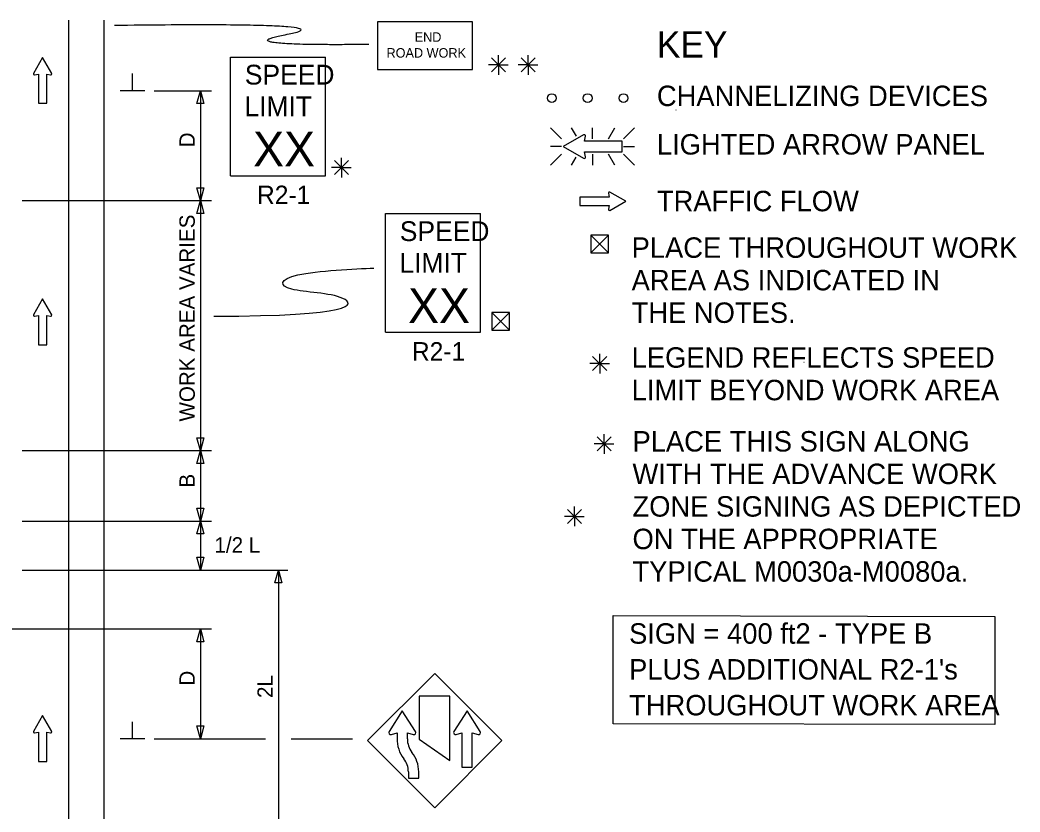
# Model space of a CAD drawing. Extents: x 16648 to 18482, y 5650 to 7013.
# Drawn here: x 16969.3 to 17424.3, y 6566.2 to 6926.4 of the extents above; entities that cross this region are included whole.
import ezdxf

# ---------------------------------------------------------------- set-up
doc = ezdxf.new("R2010")
doc.units = 0
for name, color, linetype in [('MT_SCRATCH_LEVEL_E', 7, 'Continuous'), ('PAVT_EDGE_EX', 7, 'Continuous'), ('TRAFFIC_SIGNS_PR', 7, 'Continuous'), ('TYPICAL_TEXT_DIMEN_EX', 7, 'Continuous'), ('TYPICAL_TEXT_DIMEN_PR', 7, 'Continuous')]:
    doc.layers.add(name, color=color, linetype=linetype)

msp = doc.modelspace()

# ---------------------------------------------------------------- linework, layer by layer
at = {"layer": 'MT_SCRATCH_LEVEL_E'}
for p, q in [((16979.53, 6909.41), (16975.42, 6902.17)), ((16983.68, 6902.17), (16979.53, 6909.41)), ((16975.91, 6901.48), (16977.68, 6901.8)), ((16977.68, 6901.8), (16977.68, 6888.54)), ((16981.42, 6888.54), (16981.42, 6901.8)), ((16981.42, 6901.8), (16983.2, 6901.48)), ((16977.68, 6888.54), (16981.42, 6888.54)), ((17236.96, 6847.63), (17237.27, 6845.86)), ((17244.88, 6844.01), (17237.64, 6848.12)), ((17237.27, 6845.86), (17224.01, 6845.86)), ((17224.01, 6845.86), (17224.01, 6842.11)), ((17237.64, 6839.86), (17244.88, 6844.01)), ((17224.01, 6842.11), (17237.27, 6842.11)), ((17237.27, 6842.11), (17236.96, 6840.34)), ((16979.53, 6799.6), (16975.42, 6792.36)), ((16983.68, 6792.36), (16979.53, 6799.6)), ((16975.91, 6791.67), (16977.68, 6791.99)), ((16977.68, 6791.99), (16977.68, 6778.73)), ((16981.42, 6778.73), (16981.42, 6791.99)), ((16981.42, 6791.99), (16983.2, 6791.67)), ((16977.68, 6778.73), (16981.42, 6778.73)), ((16979.53, 6610.04), (16975.42, 6602.8)), ((16983.68, 6602.8), (16979.53, 6610.04)), ((16975.91, 6602.12), (16977.68, 6602.43)), ((16977.68, 6602.43), (16977.68, 6589.18)), ((16981.42, 6589.18), (16981.42, 6602.43)), ((16981.42, 6602.43), (16983.2, 6602.12)), ((16977.68, 6589.18), (16981.42, 6589.18))]:
    msp.add_line(p, q, dxfattribs=at)
for centre, start, end in [((16975.83, 6901.94), 150.4248, 279.9638), ((16983.27, 6901.94), 260.0362, 29.7731), ((17237.41, 6847.71), 60.4248, 189.9638), ((17237.42, 6840.27), 170.0362, 299.7731), ((16975.83, 6792.13), 150.4248, 279.9638), ((16983.27, 6792.13), 260.0362, 29.7731), ((16975.83, 6602.58), 150.4248, 279.9638), ((16983.27, 6602.58), 260.0362, 29.7731)]:
    msp.add_arc(centre, 0.463, start, end, dxfattribs=at)
at = {"layer": 'PAVT_EDGE_EX'}
for p, q in [((16991.36, 6926.44), (16991.36, 5975.16)), ((17007.36, 6926.44), (17007.36, 5975.16))]:
    msp.add_line(p, q, dxfattribs=at)
at = {"layer": 'TRAFFIC_SIGNS_PR'}
for p, q in [((17065.08, 6909.61), (17108.28, 6909.61)), ((17065.08, 6855.61), (17065.08, 6909.61)), ((17108.28, 6855.61), (17108.28, 6909.61)), ((17210.69, 6877.39), (17215.62, 6872.46)), ((17222.45, 6873.57), (17220.25, 6877.39)), ((17229.77, 6872.46), (17229.77, 6877.39)), ((17237.01, 6872.46), (17239.86, 6877.39)), ((17243.92, 6872.46), (17248.86, 6877.39)), ((17215.62, 6868.9), (17210.69, 6868.9)), ((17243.92, 6868.9), (17248.86, 6868.9)), ((17210.69, 6860.41), (17215.62, 6865.34)), ((17220.2, 6860.41), (17222.32, 6864.07)), ((17229.77, 6865.34), (17229.77, 6860.41)), ((17239.9, 6860.41), (17237.05, 6865.34)), ((17243.92, 6865.34), (17248.86, 6860.41)), ((17065.08, 6855.61), (17108.28, 6855.61)), ((17135.57, 6838.41), (17178.77, 6838.41)), ((17135.57, 6784.41), (17135.57, 6838.41)), ((17178.77, 6784.41), (17178.77, 6838.41)), ((17135.57, 6784.41), (17178.77, 6784.41)), ((17157.98, 6629.21), (17127.43, 6598.66)), ((17188.53, 6598.66), (17157.98, 6629.21)), ((17127.43, 6598.66), (17157.98, 6568.11)), ((17157.98, 6568.11), (17188.53, 6598.66))]:
    msp.add_line(p, q, dxfattribs=at)
for points in [[(17131.96, 6904), (17175.16, 6904), (17175.16, 6925.6), (17131.96, 6925.6)], [(17150.88, 6618.83), (17150.88, 6599.32), (17164.84, 6589.62), (17164.84, 6618.83)]]:
    msp.add_lwpolyline(points, close=True, dxfattribs=at)
for points in [[(17225.7, 6874.18), (17216.41, 6868.9), (17225.7, 6863.58)], [(17226.58, 6864.21), (17226.18, 6866.47), (17243.19, 6866.47), (17243.19, 6871.28), (17226.18, 6871.28), (17226.58, 6873.56)], [(17149.2, 6602.83), (17143.2, 6612.24), (17137.21, 6602.83)], [(17178.7, 6602.83), (17172.71, 6612.24), (17166.72, 6602.83)], [(17138.26, 6601.41), (17140.84, 6602.12), (17140.84, 6599.61)], [(17145.56, 6599.49), (17145.56, 6602.12), (17148.15, 6601.41)], [(17167.77, 6601.41), (17170.35, 6602.12), (17170.35, 6586.59), (17175.07, 6586.59), (17175.07, 6602.12), (17177.66, 6601.41)], [(17145.98, 6584.47), (17145.97, 6581.49), (17150.7, 6581.49), (17150.7, 6584.47)]]:
    msp.add_lwpolyline(points, dxfattribs=at)
for centre in [(17211.26, 6890.93), (17227.56, 6890.93), (17243.86, 6890.93)]:
    msp.add_circle(centre, 2, dxfattribs=at)
for centre, radius, start, end in [((17225.99, 6873.65), 0.598, 350.7308, 118.8916), ((17225.99, 6864.1), 0.597, 241.4833, 9.9593), ((17138.01, 6602.32), 0.945, 147.5204, 285.3986), ((17148.4, 6602.32), 0.947, 254.6828, 32.2708), ((17159.16, 6609.16), 11.81, 212.4569, 212.4665), ((17167.52, 6602.32), 0.946, 147.5497, 285.3316), ((17177.91, 6602.32), 0.943, 254.6778, 32.4665), ((17188.67, 6609.16), 11.81, 212.4569, 212.4665), ((17155, 6599.19), 14.17, 178.3293, 218.5427), ((17155, 6599.19), 9.45, 178.1936, 218.5465), ((17133.75, 6599.86), 11.81, 358.1894, 0.0048), ((17145.03, 6590.01), 11.81, 74.68, 74.6808), ((17136.52, 6584.47), 14.17, 0, 38.5422), ((17136.52, 6584.47), 9.45, 0, 38.5457)]:
    msp.add_arc(centre, radius, start, end, dxfattribs=at)
msp.add_open_spline([(17127.94, 6915.32), (17061.52, 6914.54), (17120.27, 6925.35), (17012.29, 6923.93)], degree=2, dxfattribs=at)
at = {"layer": 'TYPICAL_TEXT_DIMEN_EX'}
msp.add_lwpolyline([(17239.16, 6655.51), (17412.83, 6655.12), (17412.83, 6605.93), (17239.16, 6606.31)], close=True, dxfattribs=at)
at = {"layer": 'TYPICAL_TEXT_DIMEN_PR'}
for p, q in [((17183.74, 6909.19), (17190.11, 6902.81)), ((17190.11, 6909.19), (17183.74, 6902.81)), ((17186.92, 6906), (17186.92, 6910.45)), ((17197.24, 6909.19), (17203.62, 6902.81)), ((17203.62, 6909.19), (17197.24, 6902.81)), ((17200.43, 6906), (17200.43, 6910.45)), ((17020.48, 6894.29), (17020.48, 6902.08)), ((17186.92, 6906), (17182.39, 6906)), ((17186.92, 6906), (17190.11, 6906)), ((17186.92, 6906), (17191.4, 6906)), ((17186.92, 6906), (17186.92, 6901.5)), ((17200.43, 6906), (17195.9, 6906)), ((17200.43, 6906), (17203.62, 6906)), ((17200.43, 6906), (17204.91, 6906)), ((17200.43, 6906), (17200.43, 6901.5)), ((17026.11, 6894.29), (17014.86, 6894.29)), ((17030.36, 6894.29), (17056.36, 6894.29)), ((17049.79, 6888.43), (17051.36, 6894.29)), ((17051.36, 6894.29), (17051.36, 6844.29)), ((17051.36, 6894.29), (17052.93, 6888.43)), ((17051.36, 6888.43), (17049.79, 6888.43)), ((17052.93, 6888.43), (17051.36, 6888.43)), ((17112.35, 6862.56), (17118.72, 6856.18)), ((17118.72, 6862.56), (17112.35, 6856.18)), ((17115.53, 6859.37), (17115.53, 6863.82)), ((17115.53, 6859.37), (17111, 6859.37)), ((17115.53, 6859.37), (17118.72, 6859.37)), ((17115.53, 6859.37), (17120.01, 6859.37)), ((17115.53, 6859.37), (17115.53, 6854.87)), ((17051.36, 6844.29), (17049.79, 6850.15)), ((17049.79, 6850.15), (17051.36, 6850.15)), ((17051.36, 6850.15), (17052.93, 6850.15)), ((17052.93, 6850.15), (17051.36, 6844.29)), ((16970.29, 6844.29), (17056.36, 6844.29)), ((17049.79, 6838.43), (17051.36, 6844.29)), ((17051.36, 6844.29), (17051.36, 6730.57)), ((17051.36, 6844.29), (17052.93, 6838.43)), ((17051.36, 6838.43), (17049.79, 6838.43)), ((17052.93, 6838.43), (17051.36, 6838.43)), ((17229.05, 6828.52), (17237.05, 6820.52)), ((17229.05, 6820.52), (17237.05, 6828.52)), ((17183.93, 6793.35), (17191.93, 6785.35)), ((17183.93, 6785.35), (17191.93, 6793.35)), ((17233.01, 6770.17), (17228.48, 6770.17)), ((17229.82, 6773.36), (17236.2, 6766.98)), ((17236.2, 6773.36), (17229.82, 6766.98)), ((17233.01, 6770.17), (17233.01, 6774.63)), ((17233.01, 6770.17), (17236.2, 6770.17)), ((17233.01, 6770.17), (17237.49, 6770.17)), ((17233.01, 6770.17), (17233.01, 6765.67)), ((17051.36, 6730.57), (17049.79, 6736.43)), ((17049.79, 6736.43), (17051.36, 6736.43)), ((17051.36, 6736.43), (17052.93, 6736.43)), ((17052.93, 6736.43), (17051.36, 6730.57)), ((17231.82, 6736.83), (17238.2, 6730.45)), ((17238.2, 6736.83), (17231.82, 6730.45)), ((17235.01, 6733.64), (17235.01, 6738.1)), ((16970.29, 6730.57), (17056.36, 6730.57)), ((17049.79, 6724.7), (17051.36, 6730.57)), ((17051.36, 6730.57), (17051.36, 6698.49)), ((17051.36, 6730.57), (17052.93, 6724.7)), ((17235.01, 6733.64), (17230.48, 6733.64)), ((17235.01, 6733.64), (17238.2, 6733.64)), ((17235.01, 6733.64), (17239.49, 6733.64)), ((17235.01, 6733.64), (17235.01, 6729.14)), ((17051.36, 6724.7), (17049.79, 6724.7)), ((17052.93, 6724.7), (17051.36, 6724.7)), ((17051.36, 6698.49), (17049.79, 6704.35)), ((17049.79, 6704.35), (17051.36, 6704.35)), ((17051.36, 6705.58), (17051.36, 6701.99)), ((17051.36, 6704.35), (17052.93, 6704.35)), ((17052.93, 6704.35), (17051.36, 6698.49)), ((17218.32, 6703.83), (17224.69, 6697.45)), ((17224.69, 6703.83), (17218.32, 6697.45)), ((17221.5, 6700.64), (17221.5, 6705.1)), ((16970.29, 6698.49), (17056.36, 6698.49)), ((17049.79, 6692.63), (17051.36, 6698.49)), ((17051.36, 6698.49), (17051.36, 6676.24)), ((17051.36, 6698.49), (17052.93, 6692.63)), ((17221.5, 6700.64), (17216.97, 6700.64)), ((17221.5, 6700.64), (17224.69, 6700.64)), ((17221.5, 6700.64), (17225.98, 6700.64)), ((17221.5, 6700.64), (17221.5, 6696.14)), ((17051.36, 6692.63), (17049.79, 6692.63)), ((17052.93, 6692.63), (17051.36, 6692.63)), ((17051.36, 6676.24), (17049.79, 6682.11)), ((17049.79, 6682.11), (17051.36, 6682.11)), ((17051.36, 6682.11), (17052.93, 6682.11)), ((17052.93, 6682.11), (17051.36, 6676.24)), ((16970.29, 6676.24), (17091.17, 6676.24)), ((17085.27, 6670.38), (17086.84, 6676.24)), ((17086.84, 6676.24), (17086.84, 6558.37)), ((17086.84, 6676.24), (17088.41, 6670.38)), ((17086.84, 6670.38), (17085.27, 6670.38)), ((17088.41, 6670.38), (17086.84, 6670.38)), ((16951.51, 6649.44), (17056.36, 6649.44)), ((17049.79, 6643.58), (17051.36, 6649.44)), ((17051.36, 6649.44), (17051.36, 6599.44)), ((17051.36, 6649.44), (17052.93, 6643.58)), ((17051.36, 6643.58), (17049.79, 6643.58)), ((17052.93, 6643.58), (17051.36, 6643.58)), ((17020.48, 6599.44), (17020.48, 6607.22)), ((17051.36, 6599.44), (17049.79, 6605.3)), ((17049.79, 6605.3), (17051.36, 6605.3)), ((17051.36, 6605.3), (17052.93, 6605.3)), ((17052.93, 6605.3), (17051.36, 6599.44)), ((17026.11, 6599.44), (17014.86, 6599.44)), ((17030.36, 6599.44), (17080.98, 6599.44)), ((17092.7, 6599.44), (17120.51, 6599.44))]:
    msp.add_line(p, q, dxfattribs=at)
for points in [[(17229.05, 6828.52), (17229.05, 6820.52), (17237.05, 6820.52), (17237.05, 6828.52)], [(17183.93, 6793.35), (17183.93, 6785.35), (17191.93, 6785.35), (17191.93, 6793.35)]]:
    msp.add_lwpolyline(points, close=True, dxfattribs=at)
for points, degree in [([(17267.72, 6885.65), (17267.73, 6885.65), (17267.74, 6885.65), (17267.74, 6885.65)], 2), ([(17057.4, 6791.72), (17121.98, 6791.72), (17121.98, 6802.48), (17087.07, 6802.48), (17087.07, 6811.56), (17121.76, 6813.31), (17130.31, 6813.6)], 3), ([(17325.96, 6770.76), (17325.98, 6770.76), (17325.99, 6770.76), (17325.99, 6770.76)], 2)]:
    msp.add_open_spline(points, degree=degree, dxfattribs=at)

# ---------------------------------------------------------------- texts
at = {"layer": 'TRAFFIC_SIGNS_PR'}
for s, height, p in [('END', 4.31, (17148.84, 6916.52)), ('ROAD WORK', 4.31, (17136.02, 6909.34)), ('SPEED', 9, (17071.56, 6897.08)), ('LIMIT', 9, (17071.38, 6882.68)), ('XX', 15.785, (17075.33, 6859.84)), ('R2-1', 8.37, (17077.09, 6842.74)), ('SPEED', 9, (17142.06, 6825.88)), ('LIMIT', 9, (17141.88, 6811.48)), ('XX', 15.785, (17145.83, 6788.64)), ('R2-1', 8.37, (17147.58, 6771.54)), ('PLACE THIS SIGN ALONG', 9.3, (17247.95, 6730.14)), ('WITH THE ADVANCE WORK', 9.3, (17247.95, 6715.34)), ('ZONE SIGNING AS DEPICTED', 9.3, (17247.95, 6700.54)), ('ON THE APPROPRIATE', 9.3, (17247.95, 6685.74)), ('TYPICAL M0030a-M0080a.', 9.3, (17247.95, 6670.94))]:
    msp.add_text(s, height=height, dxfattribs=at).set_placement(p)
at = {"layer": 'TYPICAL_TEXT_DIMEN_EX'}
for s, height, p in [('KEY', 12, (17259.05, 6909.34)), ('CHANNELIZING DEVICES', 9.3, (17259.05, 6887.29)), ('LIGHTED ARROW PANEL', 9.3, (17259.05, 6865.24)), ('TRAFFIC FLOW', 9.3, (17259.05, 6839.44)), ('PLACE THROUGHOUT WORK', 9.3, (17247.55, 6818.26)), ('AREA AS INDICATED IN', 9.3, (17247.55, 6803.46)), ('THE NOTES.', 9.3, (17247.55, 6788.66)), ('LEGEND REFLECTS SPEED', 9.3, (17247.56, 6768.27)), ('LIMIT BEYOND WORK AREA', 9.3, (17247.56, 6753.47)), ('SIGN = 400 ft2 - TYPE B', 9.3, (17246.39, 6642.72)), ("PLUS ADDITIONAL R2-1's", 9.3, (17246.39, 6626.42)), ('THROUGHOUT WORK AREA', 9.3, (17246.39, 6610.12))]:
    msp.add_text(s, height=height, dxfattribs=at).set_placement(p)
at = {"layer": 'TYPICAL_TEXT_DIMEN_PR'}
for s, p in [('D', (17048.8, 6868.51)), ('WORK AREA VARIES', (17048.8, 6743.79)), ('B', (17048.8, 6713.76)), ('D', (17048.8, 6623.66)), ('2L', (17084.28, 6618.03))]:
    msp.add_text(s, height=7, rotation=90, dxfattribs=at).set_placement(p)
msp.add_text('1/2 L', height=7, dxfattribs=at).set_placement((17057.76, 6684.16))

doc.saveas('drawing.dxf')
